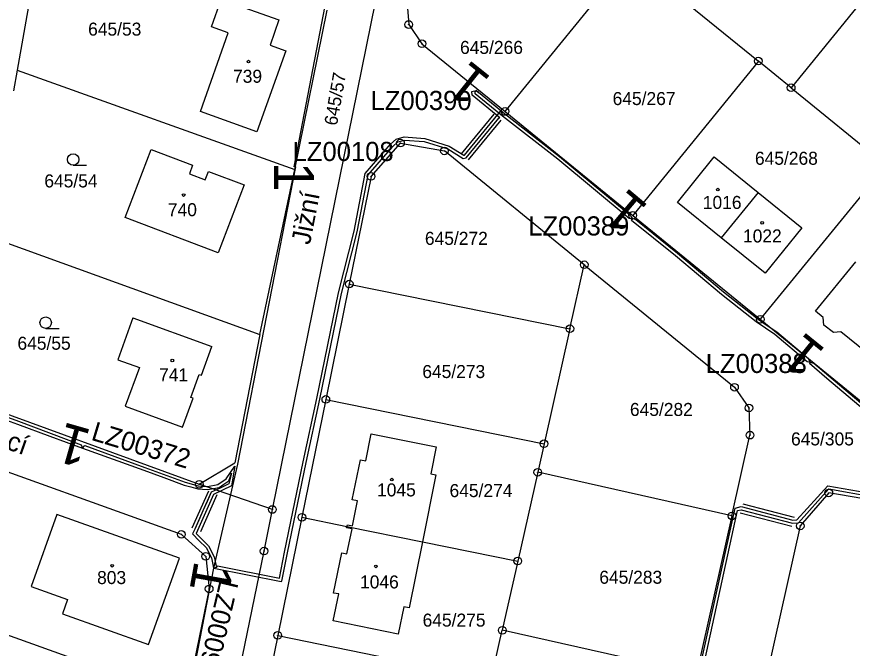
# Model space of a CAD drawing. Extents: x -738131 to -734179, y -1033447 to -1030078.
# Drawn here: x -735850.6 to -735741.5, y -1032867.1 to -1032784.6 of the extents above; entities that cross this region are included whole.
import ezdxf

# ---------------------------------------------------------------- set-up
doc = ezdxf.new("R2010")
doc.units = 0
for name, color, linetype in [('ftf_2010', 7, 'Continuous'), ('ftf_2100', 7, 'Continuous'), ('ftf_2140', 7, 'Continuous'), ('ftf_3010', 7, 'Continuous'), ('ftf_3010_ftf_3010_gtda_3015_gtda_3015_1', 7, 'Continuous'), ('ftf_3210', 7, 'Continuous'), ('ftf_nu', 7, 'Continuous'), ('Vrstva 1', 7, 'Continuous'), ('Vrstva 2', 7, 'Continuous'), ('Vrstva 3', 7, 'Continuous'), ('Vrstva 5', 7, 'Continuous'), ('Vrstva 8', 7, 'Continuous')]:
    doc.layers.add(name, color=color, linetype=linetype)

msp = doc.modelspace()

# ---------------------------------------------------------------- linework, layer by layer
at = {"layer": 'ftf_2010'}
for points in [[(-735814.42, -1032804.25), (-735807.64, -1032769.14)], [(-735770.15, -1032811.01), (-735770.65, -1032810.99), (-735779.98, -1032803.26), (-735787.2, -1032797.62), (-735790.76, -1032794.7), (-735790.78, -1032794.47), (-735790.63, -1032794.3)], [(-735746.97, -1032829.81), (-735747.4, -1032829.7), (-735751.62, -1032826.16), (-735752.83, -1032825.33), (-735754.05, -1032824.5), (-735758.59, -1032820.92), (-735764.61, -1032815.88), (-735770.34, -1032811.25), (-735770.15, -1032811.01)], [(-735722.08, -1032850.15), (-735722.62, -1032850.2), (-735724.58, -1032848.7), (-735735.63, -1032839.65), (-735744.85, -1032831.9), (-735747.1, -1032829.96), (-735746.97, -1032829.81)], [(-735865.81, -1032832.27), (-735865.62, -1032832.46), (-735865.43, -1032832.64), (-735861.85, -1032833.84), (-735858.28, -1032835.04), (-735854.42, -1032836.45), (-735850.56, -1032837.85), (-735846.3, -1032839.42), (-735842.04, -1032840.99)], [(-735842.04, -1032840.99), (-735838.04, -1032842.44), (-735834.04, -1032843.89), (-735831.41, -1032844.85), (-735828.78, -1032845.82), (-735827.9, -1032846.07), (-735827.01, -1032846.31), (-735826.36, -1032846.36), (-735825.71, -1032846.41), (-735824.96, -1032846.28), (-735824.21, -1032846.14), (-735823.58, -1032845.7), (-735822.94, -1032845.26), (-735822.76, -1032844.77), (-735822.57, -1032844.28), (-735822.76, -1032844.97), (-735822.94, -1032845.66), (-735824.09, -1032846.21), (-735825.24, -1032846.76), (-735826.32, -1032849.18), (-735827.39, -1032851.6), (-735827.54, -1032851.91), (-735827.69, -1032852.21), (-735826.81, -1032853.09), (-735825.92, -1032853.98), (-735825.22, -1032855.33), (-735825.08, -1032855.99), (-735824.95, -1032856.66)], [(-735762.13, -1032872.86), (-735761.6, -1032872.99), (-735761.34, -1032871.9), (-735761.3, -1032871.42), (-735761.26, -1032870.37), (-735761.04, -1032869.89), (-735756.48, -1032849.16), (-735756.03, -1032849.04), (-735749.31, -1032850.8), (-735748.55, -1032850.74), (-735744.57, -1032846.33), (-735738.79, -1032847.35)], [(-735824.95, -1032856.66), (-735832.11, -1032893.62)]]:
    msp.add_lwpolyline(points, dxfattribs=at)
at = {"layer": 'ftf_2100'}
for points in [[(-735824.91, -1032856.67), (-735816.11, -1032858.42), (-735816, -1032858.36), (-735815.27, -1032854.66), (-735812.82, -1032842.87), (-735811.06, -1032834.61), (-735808.21, -1032820.8), (-735806.17, -1032812.74), (-735804.74, -1032805.31), (-735801.54, -1032801.59), (-735800.87, -1032801), (-735800, -1032800.75), (-735797.43, -1032800.95), (-735794.32, -1032801.91), (-735792.33, -1032803.17), (-735791.95, -1032803.08), (-735787.66, -1032797.89), (-735787.56, -1032797.84), (-735791.14, -1032794.9), (-735791.19, -1032794.42), (-735790.63, -1032794.3)], [(-735814.22, -1032804.25), (-735821.8, -1032843.1), (-735824.95, -1032856.66)]]:
    msp.add_lwpolyline(points, dxfattribs=at)
at = {"layer": 'ftf_2140'}
for points in [[(-735770.15, -1032811.01), (-735770.5, -1032810.6), (-735779.73, -1032802.95), (-735786.95, -1032797.31), (-735790.32, -1032794.54), (-735790.63, -1032794.3), (-735790.32, -1032794.55)], [(-735824.56, -1032856.58), (-735824.44, -1032856.35), (-735816.33, -1032857.96), (-735815.66, -1032854.58), (-735813.21, -1032842.79), (-735811.45, -1032834.53), (-735808.6, -1032820.71), (-735806.56, -1032812.65), (-735805.12, -1032805.13), (-735801.82, -1032801.31), (-735801.07, -1032800.64), (-735800.04, -1032800.35), (-735797.35, -1032800.55), (-735794.15, -1032801.54), (-735792.26, -1032802.74), (-735792.17, -1032802.72), (-735787.39, -1032796.95)], [(-735746.97, -1032829.81), (-735747.22, -1032829.34), (-735751.38, -1032825.84), (-735752.61, -1032825), (-735753.81, -1032824.18), (-735758.34, -1032820.61), (-735764.35, -1032815.57), (-735769.78, -1032811.19), (-735770.15, -1032811.01)], [(-735722.08, -1032850.15), (-735722.5, -1032849.79), (-735724.33, -1032848.38), (-735735.38, -1032839.34), (-735744.59, -1032831.6), (-735746.53, -1032829.92), (-735746.97, -1032829.81)], [(-735865.81, -1032832.27), (-735865.53, -1032831.98), (-735865.22, -1032832.29), (-735858.15, -1032834.66), (-735850.42, -1032837.47), (-735842.21, -1032840.55), (-735842.04, -1032840.99)], [(-735842.04, -1032840.99), (-735841.77, -1032840.67), (-735841.77, -1032840.66), (-735833.9, -1032843.51), (-735828.66, -1032845.44), (-735826.94, -1032845.91), (-735825.73, -1032846.01), (-735824.37, -1032845.76), (-735823.27, -1032845), (-735822.16, -1032843.36), (-735822.6, -1032845.94), (-735824.93, -1032847.06), (-735827.03, -1032851.77), (-735827.2, -1032852.13), (-735825.59, -1032853.74), (-735824.84, -1032855.2), (-735824.56, -1032856.58), (-735824.95, -1032856.66)], [(-735762.04, -1032872.47), (-735762.13, -1032872.86), (-735761.74, -1032871.84), (-735761.7, -1032871.39), (-735761.65, -1032870.28), (-735761.42, -1032869.76), (-735756.82, -1032848.83), (-735756.03, -1032848.63), (-735749.27, -1032850.39), (-735748.74, -1032850.35), (-735744.72, -1032845.9), (-735738.68, -1032846.96), (-735737.55, -1032847.47), (-735724.37, -1032858.43), (-735723.53, -1032858.96), (-735723.13, -1032859.25), (-735722.7, -1032859.55), (-735714.65, -1032866.02), (-735705.66, -1032873.4), (-735700.66, -1032866.99), (-735699.97, -1032865.87)]]:
    msp.add_lwpolyline(points, dxfattribs=at)
at = {"layer": 'ftf_3210'}
for p, q in [((-735825.61, -1032846.6), (-735827.76, -1032851.44)), ((-735824.51, -1032847.08), (-735826.66, -1032851.92))]:
    msp.add_line(p, q, dxfattribs=at)
for points in [[(-735792.56, -1032802.57), (-735788.27, -1032797.38)], [(-735791.64, -1032803.34), (-735787.35, -1032798.15)], [(-735825.24, -1032846.76), (-735825.78, -1032847.97), (-735826.32, -1032849.18), (-735826.85, -1032850.39), (-735827.39, -1032851.6)], [(-735755.82, -1032848.27), (-735749.11, -1032850.02)], [(-735756.13, -1032849.43), (-735749.41, -1032851.18)]]:
    msp.add_lwpolyline(points, dxfattribs=at)
at = {"layer": 'Vrstva 1'}
for points in [[(-735817.24, -1032849.01), (-735797.93, -1032753.98)], [(-735727.92, -1032767.43), (-735749.49, -1032793.92)], [(-735847.22, -1032772.64), (-735850.58, -1032791.63)], [(-735786.85, -1032797.02), (-735770.43, -1032776.86)], [(-735766.55, -1032780.02), (-735753.76, -1032790.44)], [(-735825.22, -1032785.96), (-735823.93, -1032782.36)], [(-735823.93, -1032782.36), (-735816.39, -1032785.05)], [(-735799.7, -1032782.47), (-735799.45, -1032785.66)], [(-735814.33, -1032804.6), (-735810.09, -1032783.8)], [(-735816.39, -1032785.05), (-735817.56, -1032788.35)], [(-735799.45, -1032785.66), (-735797.71, -1032788.17)], [(-735826.64, -1032797.02), (-735823.01, -1032786.73)], [(-735823.01, -1032786.73), (-735825.22, -1032785.96)], [(-735817.56, -1032788.35), (-735815.51, -1032789.09)], [(-735797.71, -1032788.17), (-735786.85, -1032797.02)], [(-735815.51, -1032789.09), (-735819.28, -1032799.67)], [(-735753.76, -1032790.44), (-735770.19, -1032810.6)], [(-735749.49, -1032793.92), (-735753.76, -1032790.44)], [(-735850.58, -1032791.63), (-735851.07, -1032794.33)], [(-735850.58, -1032791.63), (-735814.33, -1032804.6)], [(-735749.49, -1032793.92), (-735737.09, -1032804.02)], [(-735819.28, -1032799.67), (-735826.64, -1032797.02)], [(-735786.85, -1032797.02), (-735770.19, -1032810.6)], [(-735836.49, -1032810.87), (-735833.09, -1032801.99)], [(-735833.09, -1032801.99), (-735827.67, -1032804.05)], [(-735804.37, -1032805.5), (-735800.52, -1032801.15)], [(-735800.52, -1032801.15), (-735794.78, -1032802.17)], [(-735776.52, -1032817.04), (-735794.78, -1032802.17)], [(-735764.35, -1032808.9), (-735759.54, -1032802.96)], [(-735759.54, -1032802.96), (-735753.81, -1032807.59)], [(-735827.67, -1032804.05), (-735828.09, -1032805.16)], [(-735737.09, -1032804.02), (-735753.52, -1032824.17)], [(-735828.09, -1032805.16), (-735826.03, -1032805.96)], [(-735826.03, -1032805.96), (-735825.6, -1032804.84)], [(-735825.6, -1032804.84), (-735820.94, -1032806.62)], [(-735818.91, -1032826.14), (-735814.33, -1032804.6)], [(-735804.37, -1032805.5), (-735807.21, -1032819.56)], [(-735820.94, -1032806.62), (-735824.32, -1032815.5)], [(-735753.81, -1032807.59), (-735758.63, -1032813.52)], [(-735753.81, -1032807.59), (-735748.08, -1032812.22)], [(-735758.63, -1032813.52), (-735764.35, -1032808.9)], [(-735770.19, -1032810.6), (-735753.52, -1032824.17)], [(-735824.32, -1032815.5), (-735836.49, -1032810.87)], [(-735748.08, -1032812.22), (-735752.9, -1032818.16)], [(-735854.43, -1032813.32), (-735818.91, -1032826.14)], [(-735752.9, -1032818.16), (-735758.63, -1032813.52)], [(-735778.39, -1032825.4), (-735776.52, -1032817.04)], [(-735776.52, -1032817.04), (-735756.89, -1032833.04)], [(-735746.3, -1032823.09), (-735741.05, -1032816.65)], [(-735807.21, -1032819.56), (-735810.27, -1032834.63)], [(-735807.21, -1032819.56), (-735778.39, -1032825.4)], [(-735745.31, -1032823.91), (-735746.3, -1032823.09)], [(-735745.23, -1032824.92), (-735745.31, -1032823.91)], [(-735835.47, -1032823.97), (-735837.45, -1032829.45)], [(-735835.47, -1032823.97), (-735825.14, -1032827.72)], [(-735753.52, -1032824.17), (-735736.85, -1032837.75)], [(-735743.97, -1032825.9), (-735745.23, -1032824.92)], [(-735778.39, -1032825.4), (-735781.77, -1032840.42)], [(-735742.98, -1032825.8), (-735743.97, -1032825.9)], [(-735738.46, -1032829.48), (-735742.98, -1032825.8)], [(-735818.91, -1032826.14), (-735822.16, -1032842.93)], [(-735826.52, -1032831.48), (-735825.14, -1032827.72)], [(-735837.45, -1032829.45), (-735834.63, -1032830.45)], [(-735834.63, -1032830.45), (-735836.5, -1032835.5)], [(-735827.89, -1032834.37), (-735826.8, -1032831.37)], [(-735826.8, -1032831.37), (-735826.52, -1032831.48)], [(-735756.89, -1032833.04), (-735755.01, -1032835.74)], [(-735858.08, -1032834.28), (-735826.81, -1032845.72)], [(-735828.98, -1032838.24), (-735827.61, -1032834.48)], [(-735827.61, -1032834.48), (-735827.89, -1032834.37)], [(-735810.27, -1032834.63), (-735813.4, -1032850.03)], [(-735810.27, -1032834.63), (-735781.77, -1032840.42)], [(-735836.5, -1032835.5), (-735828.98, -1032838.24)], [(-735755.01, -1032835.74), (-735754.87, -1032839.3)], [(-735805.06, -1032842.65), (-735804.34, -1032839.11)], [(-735804.34, -1032839.11), (-735795.86, -1032840.84)], [(-735757.22, -1032849.85), (-735754.87, -1032839.3)], [(-735829.13, -1032852.26), (-735859.7, -1032841.3)], [(-735795.86, -1032840.84), (-735796.57, -1032844.36)], [(-735781.77, -1032840.42), (-735782.59, -1032844.15)], [(-735826.81, -1032845.72), (-735822.16, -1032842.93)], [(-735806.81, -1032847.76), (-735805.74, -1032842.51)], [(-735805.74, -1032842.51), (-735805.06, -1032842.65)], [(-735795.89, -1032844.5), (-735797.66, -1032853.22)], [(-735796.57, -1032844.36), (-735795.89, -1032844.5)], [(-735782.59, -1032844.15), (-735785.2, -1032855.74)], [(-735757.22, -1032849.85), (-735782.59, -1032844.15)], [(-735817.24, -1032849.01), (-735826.81, -1032845.72)], [(-735744.57, -1032846.85), (-735748.3, -1032851.15)], [(-735738.74, -1032847.83), (-735744.57, -1032846.85)], [(-735806.12, -1032847.88), (-735806.81, -1032847.76)], [(-735806.77, -1032851.15), (-735806.12, -1032847.88)], [(-735818.34, -1032854.44), (-735817.24, -1032849.01)], [(-735845.39, -1032849.66), (-735848.78, -1032859.07)], [(-735829.38, -1032855.38), (-735845.39, -1032849.66)], [(-735813.4, -1032850.03), (-735816.55, -1032865.45)], [(-735813.4, -1032850.03), (-735807.51, -1032851.22)], [(-735757.22, -1032849.85), (-735761.85, -1032870.48)], [(-735797.66, -1032853.22), (-735799.4, -1032861.85), (-735800.09, -1032861.72), (-735800.81, -1032865.28), (-735809.3, -1032863.57), (-735808.57, -1032860.04), (-735809.27, -1032859.92), (-735808.2, -1032854.65), (-735807.51, -1032854.81), (-735806.85, -1032851.54), (-735807.55, -1032851.39), (-735807.51, -1032851.22)], [(-735807.51, -1032851.22), (-735807.46, -1032851)], [(-735807.51, -1032851.22), (-735797.66, -1032853.22)], [(-735807.46, -1032851), (-735806.77, -1032851.15)], [(-735748.3, -1032851.15), (-735752.63, -1032870.43)], [(-735825.96, -1032855.13), (-735829.13, -1032852.26)], [(-735797.66, -1032853.22), (-735785.2, -1032855.74)], [(-735842.08, -1032970.02), (-735818.34, -1032854.44)], [(-735833.42, -1032866.65), (-735829.38, -1032855.38)], [(-735825.96, -1032855.13), (-735825.51, -1032859.38)], [(-735785.2, -1032855.74), (-735787.22, -1032864.79)], [(-735848.78, -1032859.07), (-735844.02, -1032860.77)], [(-735825.51, -1032859.38), (-735828.45, -1032873.79)], [(-735844.02, -1032860.77), (-735844.67, -1032862.65)], [(-735863.78, -1032861.12), (-735828.45, -1032873.79)], [(-735844.67, -1032862.65), (-735833.42, -1032866.65)], [(-735788.66, -1032871.16), (-735787.22, -1032864.79)], [(-735761.85, -1032870.48), (-735787.22, -1032864.79)], [(-735816.55, -1032865.45), (-735819.78, -1032881.24)], [(-735816.55, -1032865.45), (-735788.66, -1032871.16)]]:
    msp.add_lwpolyline(points, dxfattribs=at)
at = {"layer": 'Vrstva 3'}
for p, q in [((-735843.27, -1032804.05), (-735841.52, -1032804.05)), ((-735846.86, -1032825.35), (-735845.11, -1032825.35))]:
    msp.add_line(p, q, dxfattribs=at)
for centre in [(-735843.27, -1032803.3), (-735846.86, -1032824.6)]:
    msp.add_circle(centre, 0.75, dxfattribs=at)
at = {"layer": 'Vrstva 5'}
for centre in [(-735820.38, -1032790.51), (-735759.08, -1032807.23), (-735828.84, -1032807.93), (-735753.28, -1032811.57), (-735830.32, -1032829.55), (-735801.65, -1032845.11), (-735838.19, -1032856.35), (-735803.72, -1032856.44)]:
    msp.add_circle(centre, 0.175, dxfattribs=at)
at = {"layer": 'Vrstva 8'}
for centre, radius in [((-735799.45, -1032785.66), 0.5), ((-735799.45, -1032785.66), 0.0303), ((-735797.71, -1032788.17), 0.5), ((-735797.71, -1032788.17), 0.0303), ((-735753.76, -1032790.44), 0.5), ((-735753.76, -1032790.44), 0.0303), ((-735749.49, -1032793.92), 0.5), ((-735749.49, -1032793.92), 0.0303), ((-735786.85, -1032797.02), 0.5), ((-735786.85, -1032797.02), 0.0303), ((-735800.52, -1032801.15), 0.5), ((-735800.52, -1032801.15), 0.0303), ((-735794.78, -1032802.17), 0.5), ((-735794.78, -1032802.17), 0.0303), ((-735804.37, -1032805.5), 0.5), ((-735804.37, -1032805.5), 0.0303), ((-735770.19, -1032810.6), 0.5), ((-735770.19, -1032810.6), 0.0303), ((-735776.52, -1032817.04), 0.5), ((-735776.52, -1032817.04), 0.0303), ((-735807.21, -1032819.56), 0.5), ((-735807.21, -1032819.56), 0.0303), ((-735753.52, -1032824.17), 0.5), ((-735778.39, -1032825.4), 0.5), ((-735753.52, -1032824.17), 0.0303), ((-735778.39, -1032825.4), 0.0303), ((-735756.89, -1032833.04), 0.5), ((-735756.89, -1032833.04), 0.0303), ((-735810.27, -1032834.63), 0.5), ((-735810.27, -1032834.63), 0.0303), ((-735755.01, -1032835.74), 0.5), ((-735755.01, -1032835.74), 0.0303), ((-735754.87, -1032839.3), 0.5), ((-735781.77, -1032840.42), 0.5), ((-735754.87, -1032839.3), 0.0303), ((-735781.77, -1032840.42), 0.0303), ((-735782.59, -1032844.15), 0.5), ((-735782.59, -1032844.15), 0.0303), ((-735826.81, -1032845.72), 0.5), ((-735826.81, -1032845.72), 0.0303), ((-735744.57, -1032846.85), 0.5), ((-735744.57, -1032846.85), 0.0303), ((-735817.24, -1032849.01), 0.5), ((-735817.24, -1032849.01), 0.0303), ((-735813.4, -1032850.03), 0.5), ((-735813.4, -1032850.03), 0.0303), ((-735757.22, -1032849.85), 0.5), ((-735757.22, -1032849.85), 0.0303), ((-735748.3, -1032851.15), 0.5), ((-735748.3, -1032851.15), 0.0303), ((-735829.13, -1032852.26), 0.5), ((-735829.13, -1032852.26), 0.0303), ((-735818.34, -1032854.44), 0.5), ((-735818.34, -1032854.44), 0.0303), ((-735825.96, -1032855.13), 0.5), ((-735825.96, -1032855.13), 0.0303), ((-735785.2, -1032855.74), 0.5), ((-735785.2, -1032855.74), 0.0303), ((-735825.51, -1032859.38), 0.5), ((-735825.51, -1032859.38), 0.0303), ((-735787.22, -1032864.79), 0.5), ((-735816.55, -1032865.45), 0.5), ((-735816.55, -1032865.45), 0.0303), ((-735787.22, -1032864.79), 0.0303)]:
    msp.add_circle(centre, radius, dxfattribs=at)

# ---------------------------------------------------------------- texts
at = {"layer": 'ftf_3010'}
for rotation, p in [(141.4364, (-735788.51, -1032792.67)), (270, (-735817.02, -1032803.6)), (139.926, (-735767.98, -1032809.44)), (141.0044, (-735744.83, -1032828.2)), (164.0617, (-735840.7, -1032838.67)), (259.8011, (-735827.39, -1032855.56))]:
    msp.add_text('1', height=5.2, rotation=rotation, dxfattribs=at).set_placement(p)
at = {"layer": 'ftf_3010_ftf_3010_gtda_3015_gtda_3015_1'}
for s, p in [('LZ00390', (-735804.43, -1032796.83)), ('LZ00389', (-735783.83, -1032813.22)), ('LZ00388', (-735760.65, -1032831.18))]:
    msp.add_text(s, height=2.5, dxfattribs=at).set_placement(p)
for s, rotation, p in [('LZ00108', 0, (-735814.61, -1032803.49)), ('LZ00372', 343.2201, (-735841.05, -1032839.89)), ('LZ00096', 256.7296, (-735824.1, -1032858.06))]:
    msp.add_text(s, height=2.5, rotation=rotation, dxfattribs=at).set_placement(p)
at = {"layer": 'ftf_nu'}
for s, rotation, p in [('Jižní', 79.0362, (-735812.35, -1032814.52)), ('Spojovací', 340.4488, (-735863.53, -1032837.02))]:
    msp.add_text(s, height=2.5, rotation=rotation, dxfattribs=at).set_placement(p)
at = {"layer": 'Vrstva 2'}
for s, p in [('645/53', (-735841.32, -1032787.11)), ('645/266', (-735792.74, -1032789.5)), ('739', (-735822.39, -1032793.27)), ('645/267', (-735772.81, -1032796.18)), ('645/268', (-735754.22, -1032803.98)), ('645/54', (-735847.04, -1032806.94)), ('1016', (-735761.03, -1032809.75)), ('740', (-735830.9, -1032810.7)), ('645/272', (-735797.33, -1032814.44)), ('1022', (-735755.78, -1032814.13)), ('645/55', (-735850.55, -1032828.14)), ('645/273', (-735797.67, -1032831.84)), ('741', (-735832.05, -1032832.26)), ('645/282', (-735770.55, -1032836.79)), ('645/305', (-735749.51, -1032840.64)), ('1045', (-735803.58, -1032847.3)), ('645/274', (-735794.11, -1032847.39)), ('803', (-735840.15, -1032858.75)), ('1046', (-735805.8, -1032859.32)), ('645/283', (-735774.55, -1032858.71)), ('645/275', (-735797.63, -1032864.31))]:
    msp.add_text(s, height=1.7, dxfattribs=at).set_placement(p)
msp.add_text('645/57', height=1.7, rotation=80.0215, dxfattribs=at).set_placement((-735808.82, -1032798.94))

doc.saveas('drawing.dxf')
